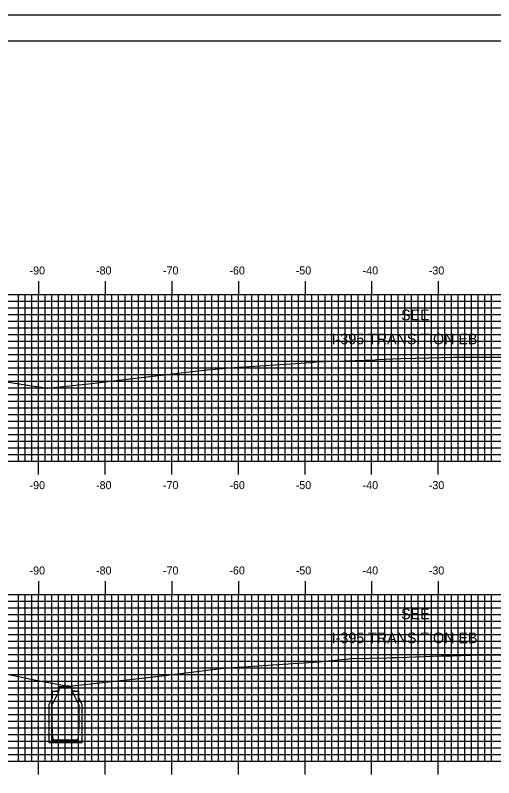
# Model space of a CAD drawing. Extents: x 844143 to 844486, y 363538 to 363758.
# Drawn here: x 844215 to 844286.8, y 363643.2 to 363757.6 of the extents above; entities that cross this region are included whole.
import ezdxf

# ---------------------------------------------------------------- set-up
doc = ezdxf.new("R2010")
doc.units = 0
for name, color, linetype in [('ANNOTATION', 7, 'Continuous'), ('BORDER', 7, 'Continuous'), ('H_V ANNOTATION', 7, 'Continuous'), ('M_Roadway_Centerline', 7, 'Continuous'), ('MAJOR', 7, 'Continuous'), ('MINOR', 7, 'Continuous'), ('PLOT BOUNDARY', 7, 'Continuous'), ('S_Drainage_CB', 7, 'Continuous'), ('S_Roadway_Centerline', 7, 'Continuous')]:
    doc.layers.add(name, color=color, linetype=linetype)

msp = doc.modelspace()

# ---------------------------------------------------------------- linework, layer by layer
at = {"layer": 'BORDER'}
msp.add_lwpolyline([(844158.85, 363543.72), (844478.85, 363543.72), (844478.85, 363753.72), (844158.85, 363753.72)], close=True, dxfattribs=at)
at = {"layer": 'MAJOR'}
for p, q in [((844218.45, 363717.73), (844218.45, 363715.72)), ((844228.45, 363717.73), (844228.45, 363715.72)), ((844238.45, 363717.73), (844238.45, 363715.72)), ((844248.45, 363717.73), (844248.45, 363715.72)), ((844258.45, 363717.73), (844258.45, 363715.72)), ((844268.45, 363717.73), (844268.45, 363715.72)), ((844278.45, 363717.73), (844278.45, 363715.72)), ((844168.45, 363715.72), (844448.45, 363715.72)), ((844168.45, 363715.72), (844448.45, 363715.72)), ((844218.45, 363690.72), (844218.45, 363715.72)), ((844228.45, 363690.72), (844228.45, 363715.72)), ((844238.45, 363690.72), (844238.45, 363715.72)), ((844248.45, 363690.72), (844248.45, 363715.72)), ((844258.45, 363690.72), (844258.45, 363715.72)), ((844268.45, 363690.72), (844268.45, 363715.72)), ((844278.45, 363690.72), (844278.45, 363715.72)), ((844168.45, 363710.72), (844448.45, 363710.72)), ((844168.45, 363705.72), (844448.45, 363705.72)), ((844168.45, 363700.72), (844448.45, 363700.72)), ((844168.45, 363695.72), (844448.45, 363695.72)), ((844168.45, 363690.72), (844448.45, 363690.72)), ((844168.45, 363690.72), (844448.45, 363690.72)), ((844218.45, 363688.72), (844218.45, 363690.72)), ((844228.45, 363688.72), (844228.45, 363690.72)), ((844238.45, 363688.72), (844238.45, 363690.72)), ((844248.45, 363688.72), (844248.45, 363690.72)), ((844258.45, 363688.72), (844258.45, 363690.72)), ((844268.45, 363688.72), (844268.45, 363690.72)), ((844278.45, 363688.72), (844278.45, 363690.72)), ((844218.45, 363672.73), (844218.45, 363670.72)), ((844228.45, 363672.73), (844228.45, 363670.72)), ((844238.45, 363672.73), (844238.45, 363670.72)), ((844248.45, 363672.73), (844248.45, 363670.72)), ((844258.45, 363672.73), (844258.45, 363670.72)), ((844268.45, 363672.73), (844268.45, 363670.72)), ((844278.45, 363672.73), (844278.45, 363670.72)), ((844168.45, 363670.72), (844448.45, 363670.72)), ((844168.45, 363670.72), (844448.45, 363670.72)), ((844218.45, 363645.72), (844218.45, 363670.72)), ((844228.45, 363645.72), (844228.45, 363670.72)), ((844238.45, 363645.72), (844238.45, 363670.72)), ((844248.45, 363645.72), (844248.45, 363670.72)), ((844258.45, 363645.72), (844258.45, 363670.72)), ((844268.45, 363645.72), (844268.45, 363670.72)), ((844278.45, 363645.72), (844278.45, 363670.72)), ((844168.45, 363665.72), (844448.45, 363665.72)), ((844168.45, 363660.72), (844448.45, 363660.72)), ((844168.45, 363655.72), (844448.45, 363655.72)), ((844168.45, 363650.72), (844448.45, 363650.72)), ((844168.45, 363645.72), (844448.45, 363645.72)), ((844168.45, 363645.72), (844448.45, 363645.72)), ((844218.45, 363643.72), (844218.45, 363645.72)), ((844228.45, 363643.72), (844228.45, 363645.72)), ((844238.45, 363643.72), (844238.45, 363645.72)), ((844248.45, 363643.72), (844248.45, 363645.72)), ((844258.45, 363643.72), (844258.45, 363645.72)), ((844268.45, 363643.72), (844268.45, 363645.72)), ((844278.45, 363643.72), (844278.45, 363645.72))]:
    msp.add_line(p, q, dxfattribs=at)
at = {"layer": 'MINOR'}
for p, q in [((844215.45, 363690.72), (844215.45, 363715.72)), ((844216.45, 363690.72), (844216.45, 363715.72)), ((844217.45, 363690.72), (844217.45, 363715.72)), ((844219.45, 363690.72), (844219.45, 363715.72)), ((844220.45, 363690.72), (844220.45, 363715.72)), ((844221.45, 363690.72), (844221.45, 363715.72)), ((844222.45, 363690.72), (844222.45, 363715.72)), ((844223.45, 363690.72), (844223.45, 363715.72)), ((844224.45, 363690.72), (844224.45, 363715.72)), ((844225.45, 363690.72), (844225.45, 363715.72)), ((844226.45, 363690.72), (844226.45, 363715.72)), ((844227.45, 363690.72), (844227.45, 363715.72)), ((844229.45, 363690.72), (844229.45, 363715.72)), ((844230.45, 363690.72), (844230.45, 363715.72)), ((844231.45, 363690.72), (844231.45, 363715.72)), ((844232.45, 363690.72), (844232.45, 363715.72)), ((844233.45, 363690.72), (844233.45, 363715.72)), ((844234.45, 363690.72), (844234.45, 363715.72)), ((844235.45, 363690.72), (844235.45, 363715.72)), ((844236.45, 363690.72), (844236.45, 363715.72)), ((844237.45, 363690.72), (844237.45, 363715.72)), ((844239.45, 363690.72), (844239.45, 363715.72)), ((844240.45, 363690.72), (844240.45, 363715.72)), ((844241.45, 363690.72), (844241.45, 363715.72)), ((844242.45, 363690.72), (844242.45, 363715.72)), ((844243.45, 363690.72), (844243.45, 363715.72)), ((844244.45, 363690.72), (844244.45, 363715.72)), ((844245.45, 363690.72), (844245.45, 363715.72)), ((844246.45, 363690.72), (844246.45, 363715.72)), ((844247.45, 363690.72), (844247.45, 363715.72)), ((844249.45, 363690.72), (844249.45, 363715.72)), ((844250.45, 363690.72), (844250.45, 363715.72)), ((844251.45, 363690.72), (844251.45, 363715.72)), ((844252.45, 363690.72), (844252.45, 363715.72)), ((844253.45, 363690.72), (844253.45, 363715.72)), ((844254.45, 363690.72), (844254.45, 363715.72)), ((844255.45, 363690.72), (844255.45, 363715.72)), ((844256.45, 363690.72), (844256.45, 363715.72)), ((844257.45, 363690.72), (844257.45, 363715.72)), ((844259.45, 363690.72), (844259.45, 363715.72)), ((844260.45, 363690.72), (844260.45, 363715.72)), ((844261.45, 363690.72), (844261.45, 363715.72)), ((844262.45, 363690.72), (844262.45, 363715.72)), ((844263.45, 363690.72), (844263.45, 363715.72)), ((844264.45, 363690.72), (844264.45, 363715.72)), ((844265.45, 363690.72), (844265.45, 363715.72)), ((844266.45, 363690.72), (844266.45, 363715.72)), ((844267.45, 363690.72), (844267.45, 363715.72)), ((844269.45, 363690.72), (844269.45, 363715.72)), ((844270.45, 363690.72), (844270.45, 363715.72)), ((844271.45, 363690.72), (844271.45, 363715.72)), ((844272.45, 363690.72), (844272.45, 363715.72)), ((844273.45, 363690.72), (844273.45, 363715.72)), ((844274.45, 363690.72), (844274.45, 363715.72)), ((844275.45, 363690.72), (844275.45, 363715.72)), ((844276.45, 363690.72), (844276.45, 363715.72)), ((844277.45, 363690.72), (844277.45, 363715.72)), ((844279.45, 363690.72), (844279.45, 363715.72)), ((844280.45, 363690.72), (844280.45, 363715.72)), ((844281.45, 363690.72), (844281.45, 363715.72)), ((844282.45, 363690.72), (844282.45, 363715.72)), ((844283.45, 363690.72), (844283.45, 363715.72)), ((844284.45, 363690.72), (844284.45, 363715.72)), ((844285.45, 363690.72), (844285.45, 363715.72)), ((844286.45, 363690.72), (844286.45, 363715.72)), ((844168.45, 363714.72), (844448.45, 363714.72)), ((844168.45, 363713.72), (844448.45, 363713.72)), ((844168.45, 363712.72), (844448.45, 363712.72)), ((844168.45, 363711.72), (844448.45, 363711.72)), ((844168.45, 363709.72), (844448.45, 363709.72)), ((844168.45, 363708.72), (844448.45, 363708.72)), ((844168.45, 363707.72), (844448.45, 363707.72)), ((844168.45, 363706.72), (844448.45, 363706.72)), ((844168.45, 363704.72), (844448.45, 363704.72)), ((844168.45, 363703.72), (844448.45, 363703.72)), ((844168.45, 363702.72), (844448.45, 363702.72)), ((844168.45, 363701.72), (844448.45, 363701.72)), ((844168.45, 363699.72), (844448.45, 363699.72)), ((844168.45, 363698.72), (844448.45, 363698.72)), ((844168.45, 363697.72), (844448.45, 363697.72)), ((844168.45, 363696.72), (844448.45, 363696.72)), ((844168.45, 363694.72), (844448.45, 363694.72)), ((844168.45, 363693.72), (844448.45, 363693.72)), ((844168.45, 363692.72), (844448.45, 363692.72)), ((844168.45, 363691.72), (844448.45, 363691.72)), ((844215.45, 363645.72), (844215.45, 363670.72)), ((844216.45, 363645.72), (844216.45, 363670.72)), ((844217.45, 363645.72), (844217.45, 363670.72)), ((844219.45, 363645.72), (844219.45, 363670.72)), ((844220.45, 363645.72), (844220.45, 363670.72)), ((844221.45, 363645.72), (844221.45, 363670.72)), ((844222.45, 363645.72), (844222.45, 363670.72)), ((844223.45, 363645.72), (844223.45, 363670.72)), ((844224.45, 363645.72), (844224.45, 363670.72)), ((844225.45, 363645.72), (844225.45, 363670.72)), ((844226.45, 363645.72), (844226.45, 363670.72)), ((844227.45, 363645.72), (844227.45, 363670.72)), ((844229.45, 363645.72), (844229.45, 363670.72)), ((844230.45, 363645.72), (844230.45, 363670.72)), ((844231.45, 363645.72), (844231.45, 363670.72)), ((844232.45, 363645.72), (844232.45, 363670.72)), ((844233.45, 363645.72), (844233.45, 363670.72)), ((844234.45, 363645.72), (844234.45, 363670.72)), ((844235.45, 363645.72), (844235.45, 363670.72)), ((844236.45, 363645.72), (844236.45, 363670.72)), ((844237.45, 363645.72), (844237.45, 363670.72)), ((844239.45, 363645.72), (844239.45, 363670.72)), ((844240.45, 363645.72), (844240.45, 363670.72)), ((844241.45, 363645.72), (844241.45, 363670.72)), ((844242.45, 363645.72), (844242.45, 363670.72)), ((844243.45, 363645.72), (844243.45, 363670.72)), ((844244.45, 363645.72), (844244.45, 363670.72)), ((844245.45, 363645.72), (844245.45, 363670.72)), ((844246.45, 363645.72), (844246.45, 363670.72)), ((844247.45, 363645.72), (844247.45, 363670.72)), ((844249.45, 363645.72), (844249.45, 363670.72)), ((844250.45, 363645.72), (844250.45, 363670.72)), ((844251.45, 363645.72), (844251.45, 363670.72)), ((844252.45, 363645.72), (844252.45, 363670.72)), ((844253.45, 363645.72), (844253.45, 363670.72)), ((844254.45, 363645.72), (844254.45, 363670.72)), ((844255.45, 363645.72), (844255.45, 363670.72)), ((844256.45, 363645.72), (844256.45, 363670.72)), ((844257.45, 363645.72), (844257.45, 363670.72)), ((844259.45, 363645.72), (844259.45, 363670.72)), ((844260.45, 363645.72), (844260.45, 363670.72)), ((844261.45, 363645.72), (844261.45, 363670.72)), ((844262.45, 363645.72), (844262.45, 363670.72)), ((844263.45, 363645.72), (844263.45, 363670.72)), ((844264.45, 363645.72), (844264.45, 363670.72)), ((844265.45, 363645.72), (844265.45, 363670.72)), ((844266.45, 363645.72), (844266.45, 363670.72)), ((844267.45, 363645.72), (844267.45, 363670.72)), ((844269.45, 363645.72), (844269.45, 363670.72)), ((844270.45, 363645.72), (844270.45, 363670.72)), ((844271.45, 363645.72), (844271.45, 363670.72)), ((844272.45, 363645.72), (844272.45, 363670.72)), ((844273.45, 363645.72), (844273.45, 363670.72)), ((844274.45, 363645.72), (844274.45, 363670.72)), ((844275.45, 363645.72), (844275.45, 363670.72)), ((844276.45, 363645.72), (844276.45, 363670.72)), ((844277.45, 363645.72), (844277.45, 363670.72)), ((844279.45, 363645.72), (844279.45, 363670.72)), ((844280.45, 363645.72), (844280.45, 363670.72)), ((844281.45, 363645.72), (844281.45, 363670.72)), ((844282.45, 363645.72), (844282.45, 363670.72)), ((844283.45, 363645.72), (844283.45, 363670.72)), ((844284.45, 363645.72), (844284.45, 363670.72)), ((844285.45, 363645.72), (844285.45, 363670.72)), ((844286.45, 363645.72), (844286.45, 363670.72)), ((844168.45, 363669.72), (844448.45, 363669.72)), ((844168.45, 363668.72), (844448.45, 363668.72)), ((844168.45, 363667.72), (844448.45, 363667.72)), ((844168.45, 363666.72), (844448.45, 363666.72)), ((844168.45, 363664.72), (844448.45, 363664.72)), ((844168.45, 363663.72), (844448.45, 363663.72)), ((844168.45, 363662.72), (844448.45, 363662.72)), ((844168.45, 363661.72), (844448.45, 363661.72)), ((844168.45, 363659.72), (844448.45, 363659.72)), ((844168.45, 363658.72), (844448.45, 363658.72)), ((844168.45, 363657.72), (844448.45, 363657.72)), ((844168.45, 363656.72), (844448.45, 363656.72)), ((844168.45, 363654.72), (844448.45, 363654.72)), ((844168.45, 363653.72), (844448.45, 363653.72)), ((844168.45, 363652.72), (844448.45, 363652.72)), ((844168.45, 363651.72), (844448.45, 363651.72)), ((844168.45, 363649.72), (844448.45, 363649.72)), ((844168.45, 363648.72), (844448.45, 363648.72)), ((844168.45, 363647.72), (844448.45, 363647.72)), ((844168.45, 363646.72), (844448.45, 363646.72))]:
    msp.add_line(p, q, dxfattribs=at)
at = {"layer": 'PLOT BOUNDARY'}
msp.add_lwpolyline([(844142.66, 363537.6), (844482.66, 363537.6), (844482.66, 363757.6), (844142.66, 363757.6)], close=True, dxfattribs=at)
at = {"layer": 'S_Drainage_CB'}
for p, q in [((844221.48, 363656.18), (844220.5, 363656.18)), ((844220.5, 363656.18), (844220.5, 363655.2)), ((844220.5, 363654.18), (844221.48, 363656.18)), ((844224.5, 363656.18), (844223.48, 363656.18)), ((844223.48, 363656.18), (844224.5, 363654.18)), ((844224.5, 363655.2), (844224.5, 363656.18)), ((844220.5, 363655.2), (844220.01, 363654.18)), ((844224.99, 363654.18), (844224.5, 363655.2)), ((844220.01, 363654.18), (844220.01, 363648.54)), ((844220.5, 363650.87), (844220.5, 363654.18)), ((844224.5, 363654.18), (844224.5, 363650.87)), ((844224.99, 363648.54), (844224.99, 363654.18)), ((844220.66, 363648.86), (844220.5, 363650.87)), ((844224.5, 363650.87), (844224.34, 363648.86)), ((844220.01, 363648.54), (844224.99, 363648.54)), ((844224.34, 363648.86), (844220.66, 363648.86))]:
    msp.add_line(p, q, dxfattribs=at)
msp.add_lwpolyline([(844223.98, 363656.22), (844223.48, 363656.22), (844223.48, 363656.85), (844221.48, 363656.85), (844221.48, 363656.22), (844220.99, 363656.22)], dxfattribs=at)
at = {"layer": 'S_Roadway_Centerline'}
for points in [[(844210.2, 363703.17), (844215.84, 363702.27), (844219.78, 363701.66), (844219.83, 363701.65), (844220.75, 363701.76), (844226.41, 363702.36), (844232.15, 363703.09), (844243.73, 363704.4), (844245.55, 363704.58), (844247.05, 363704.7), (844259.33, 363705.54), (844260.14, 363705.64), (844265.99, 363705.83), (844269, 363705.93), (844269.21, 363705.95), (844272.84, 363706.11), (844275.02, 363706.16), (844280.83, 363706.32), (844282.64, 363706.33), (844293.29, 363706.3)], [(844212.84, 363658.95), (844218.03, 363657.89), (844222.36, 363657.06), (844223.04, 363657.04), (844223.06, 363656.99), (844233.95, 363658.15), (844235.25, 363658.3), (844246.24, 363659.65), (844254.36, 363660.2), (844260.57, 363660.64), (844265.47, 363661.11), (844270.79, 363661.24), (844271.38, 363661.25), (844272.43, 363661.29), (844278.9, 363661.5), (844280.57, 363661.54), (844283.29, 363661.6), (844292.36, 363661.69)]]:
    msp.add_lwpolyline(points, dxfattribs=at)

# ---------------------------------------------------------------- texts
at = {"layer": 'ANNOTATION'}
for s, p in [('SEE', (844272.87, 363711.85)), ('I-395 TRANSITION EB', (844262.45, 363708.25)), ('SEE', (844272.87, 363667.01)), ('I-395 TRANSITION EB', (844262.45, 363663.41))]:
    msp.add_text(s, height=1.6, dxfattribs=at).set_placement(p)
at = {"layer": 'H_V ANNOTATION'}
for s, p in [('-90', (844217.1, 363718.72)), ('-80', (844227.08, 363718.72)), ('-70', (844237.13, 363718.72)), ('-60', (844247.1, 363718.72)), ('-50', (844257.06, 363718.72)), ('-40', (844267.1, 363718.72)), ('-30', (844277.03, 363718.72)), ('-90', (844217.1, 363686.52)), ('-80', (844227.08, 363686.52)), ('-70', (844237.13, 363686.52)), ('-60', (844247.1, 363686.52)), ('-50', (844257.06, 363686.52)), ('-40', (844267.1, 363686.52)), ('-30', (844277.03, 363686.52)), ('-90', (844217.1, 363673.72)), ('-80', (844227.08, 363673.72)), ('-70', (844237.13, 363673.72)), ('-60', (844247.1, 363673.72)), ('-50', (844257.06, 363673.72)), ('-40', (844267.1, 363673.72)), ('-30', (844277.03, 363673.72))]:
    msp.add_text(s, height=1.2, dxfattribs=at).set_placement(p)
at = {"layer": 'M_Roadway_Centerline'}
for s, p in [('C', (844272.84, 363706.11)), ('L', (844272.84, 363706.11)), ('C', (844278.89, 363661.5)), ('L', (844278.9, 363661.5))]:
    msp.add_text(s, height=0.0146, dxfattribs=at).set_placement(p)

doc.saveas('drawing.dxf')
